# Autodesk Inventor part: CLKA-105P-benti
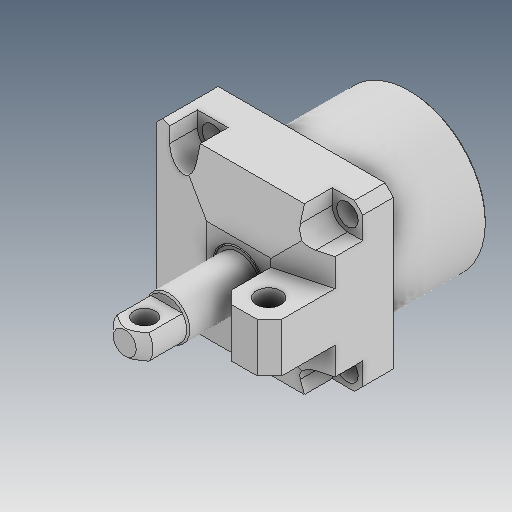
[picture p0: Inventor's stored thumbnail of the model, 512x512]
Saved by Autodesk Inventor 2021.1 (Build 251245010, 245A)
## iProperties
Created: 2018-07
Part Number: CLKA-105P-benti
Material: Ogólny
Document SubType Name: Modeling
Designer: user
Density: 1 g/cm^3
Appearance: Domyślna
Author: user
Revision Number: ÈÎºÎ
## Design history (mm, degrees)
feature "ÇÐ³ý-Ðý×ª4"
node "Bryła1"
